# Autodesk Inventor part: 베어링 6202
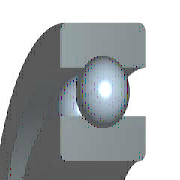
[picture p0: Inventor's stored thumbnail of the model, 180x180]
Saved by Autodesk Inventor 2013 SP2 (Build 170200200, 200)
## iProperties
Created: 2015-12
Part Number: 베어링 6202
Material: 강철, 연강
Description: 깊은 그루브 볼 베어링
Document SubType Name: Modeling
Standard: KS B 2023
Designer: mdu
Standards Organization: KS
Language: ko-KR
Size Designation: 6202 - 15 x 35 x 11
Categories: <MemberInstance><Categories><Category DisplayName="샤프트 부품" InternalName="7f7aeb1f-a693-4053-b835-cee3144e0d98" Mnemonic="SHFT"><Category DisplayName="베어링" Inter
Density: 7.86 g/cm^3
Mass: 45.8725 g
Surface Area: 51.5584 cm^2
Volume: 5.83619 cm^3
Company: 한국ATC센터
IsCustomPart: 1
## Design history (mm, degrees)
sketch "스케치" dims "d0" = 5.2 (= -0.26 x WD + 0.26 x BD)
  geometry: L1 (2.9, 12.5)-(8.1, 12.5); L2 (5.5, 12.5)-(5.5, 9.9); L3 (5.5, 12.5)-(5.5, 15.1); L4 (3.568, 10.76)-(0, 10.76); L5 (0, 7.5)-(11, 7.5); L6 (3.568, 14.24)-(0, 14.24); L7 (0, 17.5)-(11, 17.5); L8 (11, 7.5)-(11, 10.76); L9 (7.432, 10.76)-(11, 10.76); L10 (7.432, 14.24)-(11, 14.24); L11 (11, 17.5)-(11, 14.24); L12 (-1.4, 0)-(8.4, 0) reference; L13 (0, -0.3)-(0, 5.3) reference
  constraints: 22 end point, 4 point on line, 2 collinear, 2 perpendicular, 2 symmetric about line, 1 midpoint, 1 parallel, 14 other
  dimensions: "d9" = 15 diameter of L5 L12 (= WD); "d11" = 35 diameter of L7 L12 (= BD); "d12" = 11 distance between parallel lines of L8 L13 (= KB); "d13" = 21.52 diameter of L9 L12 (= 0.326 x BD + 0.674 x WD)
revolve "본체" stored, may be unused: angle "d6" = 90 deg
revolve "볼" stored, may be unused: angle "d7" = 90 deg
pattern_circular "IDS_ARRAYBALL[SIMPL:T]" dims angle "d3" = 360 deg
body "Solid1"
fillet "모깎기1" dims "d1" = 0.6 (= KRS)
other parameters: "WD" = 15 [user parameter; used in 5 equation terms], "BD" = 35 [user parameter; used in 5 equation terms], "KB" = 11 [user parameter; used in 1 equation term], "KRS" = 0.6 [user parameter; used in 1 equation term], "d4" = 0, "d5" = 0, "d8" = 0, "d14" = 0, "d15" = 0, "BBA" = 0 [user parameter], "BC0" = 3750000 [user parameter], "BC" = 7800000 [user parameter], "BR" = 17.5 (= 0.5 x BD) [user parameter], "WR" = 7.5 (= 0.5 x WD) [user parameter]
